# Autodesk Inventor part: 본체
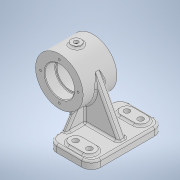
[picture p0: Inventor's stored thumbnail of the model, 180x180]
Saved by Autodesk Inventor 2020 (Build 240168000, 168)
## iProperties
Created: 2023-08
Part Number: 본체
Material: 일반
Document SubType Name: Modeling
Designer: oem
Density: 1 g/cm^3
Appearance: 기본값
Author: oem
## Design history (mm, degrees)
sketch "스케치1"
  geometry: L1 (20, -58)-(-20, -58); L2 (-35, -43)-(-35, 43); L3 (-20, 58)-(20, 58); L4 (35, 43)-(35, -43); L5 (35, -58)-(-35, 58); L6 (-35, -58)-(35, 58); A1 r 15 centre (20, -43) between (20, -58) and (35, -43); A2 r 15 centre (-20, -43) between (-35, -43) and (-20, -58); A3 r 15 centre (-20, 43) between (-20, 58) and (-35, 43); A4 r 15 centre (20, 43) between (35, 43) and (20, 58); 1 further point
  constraints: 12 end point, 8 point on circle, 8 point on line, 8 tangent, 4 centre point, 3 equal radius, 2 midpoint, 2 parallel, 1 horizontal, 1 perpendicular
  dimensions: "d0" = 70 distance of L5.end L6.end; "d1" = 116 distance of L6.start L5.end; "d2" = 15 radius of A1
extrude "돌출1" new body sketch "스케치1" distance "d3" = 12; taper "d4" = 0 deg
sketch "스케치2"
  geometry: L1 (-35, 43)-(-35, -43) reference; L2 (35, -43)-(35, 43) reference; L3 (-7, 41)-(15, 41); L4 (-7, 31)-(15, 31); L5 (15, 51)-(-7, 51); L6 (-35, 0)-(35, 0); L7 (-7, -31)-(15, -31); L8 (-7, -41)-(15, -41); L9 (15, -51)-(-7, -51); A1 r 15 centre (20, 43) between (35, 43) and (20, 58) reference; A2 r 10 centre (-7, 41) between (-7, 51) and (-7, 31); A3 r 10 centre (15, 41) between (15, 31) and (15, 51); A4 r 10 centre (-7, -41) between (-7, -31) and (-7, -51); A5 r 10 centre (15, -41) between (15, -51) and (15, -31); 4 further points
  constraints: 18 end point, 8 point on circle, 8 symmetric about line, 4 centre point, 4 tangent, 3 midpoint, 1 horizontal, 1 parallel, 2 other
  dimensions: "d6" = 11 distance of point (4, 41) L3.end; "d7" = 20 diameter of A3; "d8" = 41 vertical distance of point (0, 0) point (4, 41); "d9" = 20 distance from line of L2 L3.end
extrude "돌출2" join sketch "스케치2" distance "d10" = 3; taper "d11" = 0 deg
sketch "스케치3"
  geometry: L1 (-20, 0)-(-35, 0) reference; L2 (-35, 0)-(-35, 12) reference; L3 (-20, 12)-(-35, 12) reference; L4 (-20, 0)-(-20, 12) reference; L5 (20, 0)-(-20, 0) reference; L6 (-20, 0)-(-20, 12) reference; L7 (20, 12)-(-20, 12) reference; L8 (20, 0)-(20, 12) reference; L9 (35, 0)-(20, 0) reference; L10 (20, 0)-(20, 12) reference; L11 (35, 12)-(20, 12) reference; L12 (35, 0)-(35, 12) reference; C1 r 38 at (-47, 70); 1 further point
  constraints: 1 centre point
  dimensions: "d12" = 76 diameter of C1; "d13" = 70 distance from line of L1 C1.centre; "d14" = 82 distance from line of L12 C1.centre
extrude "돌출3" join sketch "스케치3" stored distance "d15" = 54; taper "d16" = 0 deg
sketch "스케치4"
  geometry: C1 r 38 at (0, 0) reference; C2 r 23.5 at (0, 0); 1 further point
  constraints: 1 centre point, 1 coincident
  dimensions: "d17" = 47 diameter of C2
extrude "돌출4" cut sketch "스케치4" distance "d18" = 17; taper "d19" = 0 deg
sketch "스케치5"
  geometry: C1 r 23.5 at (0, 0) reference; C2 r 20.5 at (0, 0); 1 further point
  constraints: 1 centre point, 1 coincident
  dimensions: "d20" = 41 diameter of C2
extrude "돌출5" cut sketch "스케치5" distance "d21" = 10; taper "d22" = 0 deg
sketch "스케치6"
  geometry: C1 r 23.5 at (0, 0) reference; 2 further points
  constraints: 1 vertical alignment
  dimensions: "d23" = 30 distance of C1.centre point (0, 30)
hole "구멍1" sketch "스케치6" at (0, 30) diameter "d24" = 3.242; stored, may be unused: countersink angle "d28" = 90 deg, drill point angle "d30" = 118 deg; dims "d25" = 8, "d26" = 4, "d27" = 2, "d29" = 10
fillet "모깎기1" dims "d34" = 1
chamfer "모따기1" distance "d35" = 1; stored, may be unused: second distance "d36" = 2, angle "d37" = 45 deg
sketch "스케치7"
  geometry: L1 (-7, -51)-(15, -51) reference; L2 (15, -31)-(-7, -31) reference; A1 r 10 centre (-7, 41) between (-7, 51) and (-7, 31) reference; A2 r 10 centre (15, 41) between (15, 31) and (15, 51) reference; A3 r 10 centre (-7, -41) between (-7, -31) and (-7, -51) reference; A4 r 10 centre (15, -41) between (15, -51) and (15, -31) reference; 1 further point
hole "구멍2" sketch "스케치7" at (-7, 41), (15, 41), (15, -41), (-7, -41) diameter "d38" = 9; stored, may be unused: countersink angle "d42" = 90 deg, drill point angle "d44" = 118 deg; dims "d39" = 8, "d40" = 4, "d41" = 2, "d43" = 10
node "작업 평면1"
sketch "스케치8"
  geometry: L1 (9, -27)-(85, -27) reference; L2 (85, 27)-(9, 27) reference; L3 (9, -27)-(9, 27) reference; C1 r 8 at (47, 0); 1 further point
  constraints: 1 centre point
  dimensions: "d46" = 16 diameter of C1; "d47" = 27 distance from line of L1 C1.centre; "d48" = 38 distance from line of L3 C1.centre
extrude "돌출6" join sketch "스케치8" distance "d49" = 3; taper "d51" = 0 deg; dims "d50" = 5, "d52" = 0
sketch "스케치9"
  geometry: C1 r 8 at (0, 0) reference; 1 further point
hole "구멍3" sketch "스케치9" at (0, 0) diameter "d53" = 5.1881; stored, may be unused: countersink angle "d57" = 90 deg, drill point angle "d59" = 118 deg; dims "d54" = 30, "d55" = 7, "d56" = 4, "d58" = 32
sketch "스케치11"
  geometry: L1 (-20, 0)-(-35, 0) reference; L2 (-35, 0)-(-35, 12) reference; L3 (-20, 12)-(-35, 12) reference; L4 (-20, 0)-(-20, 12) reference; L5 (20, 0)-(-20, 0) reference; L6 (-20, 0)-(-20, 12) reference; L7 (20, 12)-(-20, 12) reference; L8 (20, 0)-(20, 12) reference; L9 (35, 0)-(20, 0) reference; L10 (20, 0)-(20, 12) reference; L11 (35, 12)-(20, 12) reference; L12 (35, 0)-(35, 12) reference; L13 (35, 12)-(20, 12) reference; L14 (27, 12)-(-13.471, 87.882); L15 (-35, 0)-(-35, 12) reference; L16 (-35, 12)-(-35, 33.944); A1 r 38 centre (-47, 70) between (-13.471, 87.882) and (-35, 33.944) reference; 4 further points
  constraints: 4 end point, 2 point on circle, 1 point on line, 1 tangent, 1 vertical
  dimensions: "d61" = 8 distance of L11.start L14.start
extrude "돌출7" join sketch "스케치11" stored distance "d62" = 12; taper "d63" = 0 deg
sketch "스케치14"
  geometry: L1 (86, 0)-(86, 12) reference; L2 (49, 12)-(86, 12) reference; L3 (0, 12)-(37, 12) reference; L4 (0, 0)-(0, 12) reference; L5 (79, 12)-(60.817, 40); L6 (25.183, 40)-(7, 12); L7 (-15, 0)-(0, 0) reference; L8 (0, 0)-(0, 12) reference; L9 (-15, 12)-(0, 12) reference; L10 (-15, 0)-(-15, 12) reference; L11 (86, 0)-(101, 0) reference; L12 (101, 0)-(101, 12) reference; L13 (86, 12)-(101, 12) reference; L14 (86, 0)-(86, 12) reference; L15 (60.817, 40)-(25.183, 40); L16 (37, 12)-(49, 12) reference; L17 (37, 12)-(49, 12); 1 further point
  constraints: 8 end point, 2 point on line, 1 collinear
  dimensions: "d65" = 33 deg angle of L1 L5; "d66" = 33 deg angle of L4 L6; "d68" = 22 distance from line of L12 L5.start; "d69" = 22 distance from line of L10 L6.end; "d70" = 28 vertical distance of L5.start L5.end; "d71" = 28 vertical distance of L6.start L6.end
extrude "돌출8" join sketch "스케치14" distance "d72" = 8; taper "d73" = 0 deg
sketch "스케치15"
  geometry: L1 (0, 0)-(86, 0) reference; 3 further points
  constraints: 1 midpoint, 1 vertical alignment, 1 other
  dimensions: "d74" = 19 distance from line of L1 point (43, 19)
feature "엠보싱1" sketch "스케치15" dims "d0" = 70, "d1" = 116, "d2" = 15, "d75" = 0.5, "d76" = 0
fillet "모깎기2" dims "d77" = 3
fillet "모깎기3" dims "d78" = 3
node "솔리드1"
pattern_circular "원형 패턴1" dims angle "d32" = 360 deg
mirror "미러1"
node "투영된 루프1"
node "투영된 루프2"
node "투영된 루프3"
node "투영된 루프4"
node "투영된 루프5"
node "투영된 루프6"
node "투영된 루프7"
node "투영된 루프8"
node "투영된 루프14"
node "투영된 루프15"
feature "A9D066F2-1C7D-4E18-AEED-F7BC21143FA4" dims "d38" = 9, "d39" = 8, "d40" = 4, "d41" = 2, "d42" = 90 deg, "d43" = 10, "d44" = 118 deg
other parameters: "d45" = 108
